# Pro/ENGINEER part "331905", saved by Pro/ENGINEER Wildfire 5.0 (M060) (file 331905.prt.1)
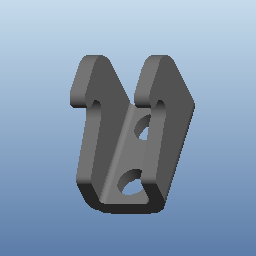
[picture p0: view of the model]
Units: PSOLunit; MM, KILOGRAM, SECS

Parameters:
  NN = "331905"
  NT = "Stainless Steel - Latch Clamps - 331-RSS Series - Cleat"
  NB = "331905"
  NBSYN = "$PN."
  LINA = "331905"
  S = "331-rss"
  PN = "331905"
  ARTICLENO = "331905"
  BOMINFO = "331905"
  CREATOR = "CADENAS GmbH"

Other parameters: A1, A2, A3, A4, A5, A6, A7, A8, A9, B1, B2, B3, B4, B5, B6, SURF_AREA, MASS

Other named items: COORD, DEF-PLANE-AXIS, DEF-PLANE-AXIS-INV, CS0, CS1, DRILLING, CS2, DRILLING_1, CLEAT_TO_HOOK_CSYS, CONN, MASS, RIGHT, TOP, FRONT, CLEAT_TO_HOOK_XPLN, CLEAT_TO_HOOK_YPLN, CLEAT_TO_HOOK_ZPLN, CLEAT_TO_HOOK_ZAXS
